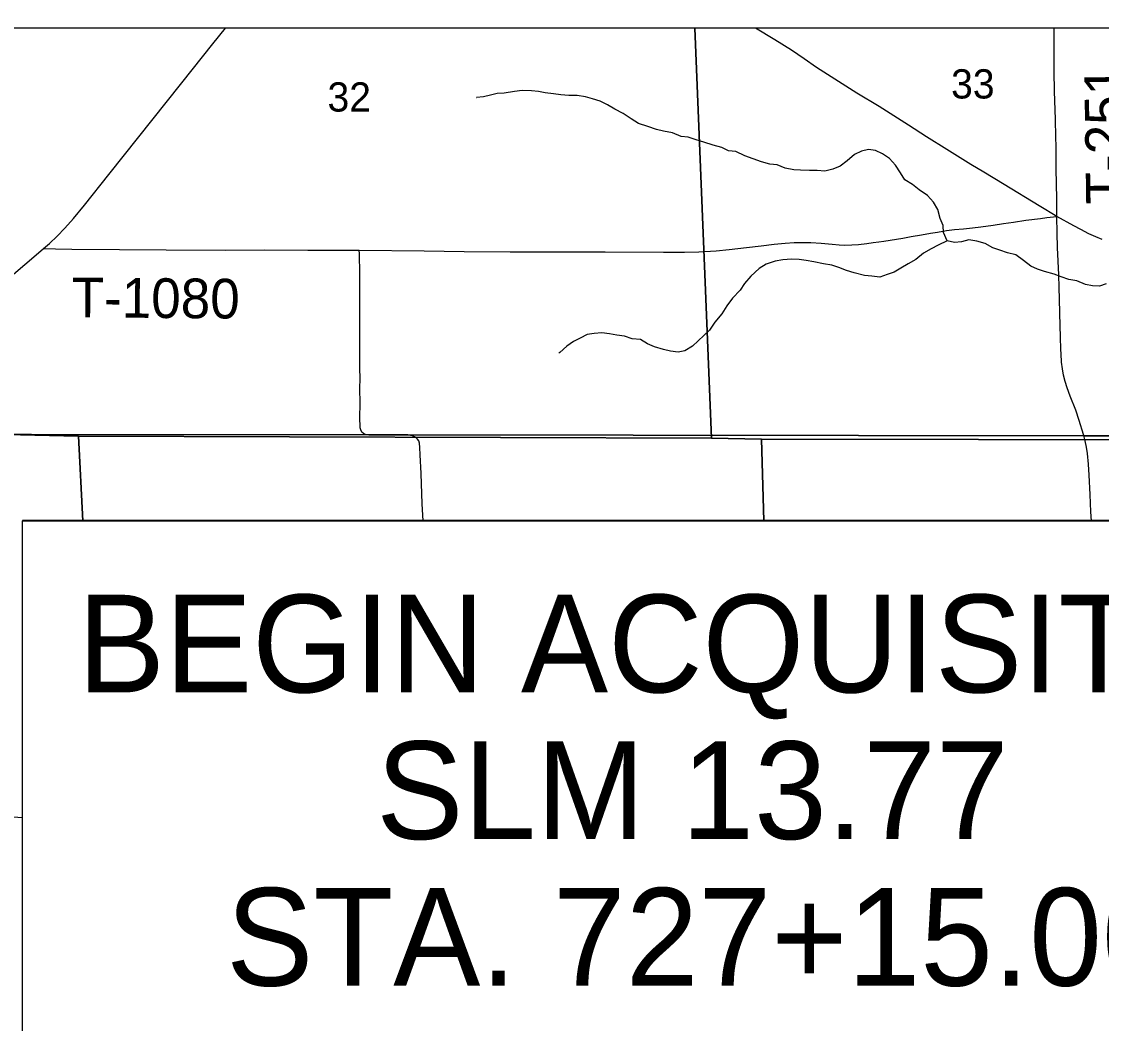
# Model space of a CAD drawing. Extents: x 0 to 34, y 0 to 22.
# Drawn here: x 4.127 to 5.673, y 16.027 to 17.462 of the extents above; entities that cross this region are included whole.
import ezdxf

# ---------------------------------------------------------------- set-up
doc = ezdxf.new("R2010")
doc.units = 0
for name, color, linetype in [('Default', 7, 'Continuous'), ('GM_X_County_Road', 7, 'Continuous'), ('GM_X_Interstate_Route', 7, 'Continuous'), ('GM_X_Minor_River', 7, 'Continuous'), ('GM_X_Section', 7, 'Continuous'), ('GM_X_Section_Text', 7, 'Continuous'), ('GM_X_State_Route', 7, 'Continuous'), ('GM_X_Township_Road', 7, 'Continuous'), ('GM_X_Township_Road_Text', 7, 'Continuous'), ('GM_X_US_Route', 7, 'Continuous'), ('SH_Text', 7, 'Continuous')]:
    doc.layers.add(name, color=color, linetype=linetype)

msp = doc.modelspace()

# ---------------------------------------------------------------- linework, layer by layer
at = {"layer": 'Default'}
for points in [[(4.0336, 18.2003), (5.9872, 18.2003), (5.9872, 17.4527), (4.0336, 17.4527)], [(4.1282, 16.747), (6.0753, 16.747), (6.0753, 16), (6.0818, 16), (6.0818, 16.7475), (4.1282, 16.7475)], [(4.1282, 16.747), (6.0818, 16.747), (6.0818, 15.9995), (4.1282, 15.9995)]]:
    msp.add_lwpolyline(points, close=True, dxfattribs=at)
at = {"layer": 'GM_X_County_Road'}
for points in [[(5.6485, 16.8672), (5.6483, 16.8682), (5.6477, 16.8705), (5.6414, 16.8909), (5.6363, 16.9056), (5.6285, 16.9258), (5.6242, 16.9376), (5.6214, 16.9465), (5.6191, 16.9556), (5.6174, 16.9648), (5.6161, 16.9741), (5.6153, 16.9864), (5.6151, 16.9926), (5.6146, 17.0107), (5.6141, 17.0263), (5.6136, 17.0451), (5.613, 17.0647), (5.6126, 17.081), (5.6121, 17.0991), (5.6112, 17.1189), (5.6105, 17.1383), (5.6099, 17.1588), (5.6094, 17.183)], [(5.6589, 16.747), (5.6581, 16.7599), (5.6572, 16.7848), (5.6556, 16.8126), (5.6547, 16.8281), (5.6532, 16.8435), (5.6518, 16.8526), (5.6499, 16.8616), (5.6485, 16.8672)]]:
    msp.add_lwpolyline(points, dxfattribs=at)
at = {"layer": 'GM_X_Interstate_Route'}
for points in [[(3.6554, 16.8713), (4.6269, 16.8701), (4.6731, 16.8702), (4.6802, 16.8702), (5.6481, 16.8687), (5.8525, 16.8686)], [(5.8525, 16.8686), (5.6481, 16.8687), (4.6802, 16.8702), (4.6731, 16.8702), (4.6269, 16.8701), (3.6554, 16.8713)]]:
    msp.add_lwpolyline(points, dxfattribs=at)
at = {"layer": 'GM_X_Minor_River'}
for points in [[(5.68, 17.0862), (5.6705, 17.0832), (5.6603, 17.0837), (5.6504, 17.0853), (5.638, 17.0907), (5.6266, 17.0924), (5.6157, 17.0963), (5.6055, 17.1005), (5.5915, 17.1041), (5.5817, 17.1072), (5.5719, 17.1119), (5.5614, 17.1196), (5.5508, 17.128), (5.5387, 17.1308), (5.5278, 17.1347), (5.5176, 17.1382), (5.5067, 17.1444), (5.495, 17.1475), (5.4832, 17.1495), (5.4726, 17.1466), (5.4627, 17.1456), (5.4525, 17.1479), (5.447, 17.1598), (5.4467, 17.17), (5.4422, 17.1799), (5.4389, 17.1928), (5.4326, 17.2032), (5.4239, 17.2131), (5.4123, 17.2212), (5.4025, 17.2285), (5.3916, 17.2354), (5.3856, 17.2454), (5.3785, 17.2564), (5.3695, 17.266), (5.3597, 17.2725), (5.3499, 17.2772), (5.3397, 17.2788), (5.3298, 17.2763), (5.3195, 17.2714), (5.3092, 17.2624), (5.2993, 17.2549), (5.2887, 17.2505), (5.2769, 17.2479), (5.266, 17.2488), (5.2553, 17.2485), (5.2425, 17.249), (5.2326, 17.2495), (5.2205, 17.2519), (5.2088, 17.2566), (5.1982, 17.2578), (5.1862, 17.261), (5.1745, 17.2656), (5.1624, 17.2699), (5.1499, 17.2761), (5.1393, 17.277), (5.1295, 17.2816), (5.1171, 17.2852), (5.1038, 17.2895), (5.0929, 17.2926), (5.0812, 17.2965), (5.0713, 17.2974), (5.0589, 17.3024), (5.046, 17.3048), (5.0362, 17.3072), (5.0238, 17.3119), (5.0102, 17.3158), (5, 17.3227), (4.9883, 17.3304), (4.9766, 17.3366), (4.9661, 17.3428), (4.9555, 17.3478), (4.9446, 17.3513), (4.9344, 17.3541), (4.9223, 17.3561), (4.9105, 17.3559), (4.8992, 17.3571), (4.8886, 17.3583), (4.8769, 17.36), (4.867, 17.362), (4.8572, 17.3628), (4.8439, 17.3633), (4.8326, 17.3619), (4.8182, 17.3594), (4.8079, 17.3588), (4.7984, 17.3566), (4.7886, 17.3544), (4.7783, 17.3534), (4.7787, 17.3533)], [(5.4525, 17.1479), (5.4396, 17.1416), (5.4293, 17.1364), (5.4183, 17.1301), (5.4076, 17.1214), (5.3966, 17.1151), (5.3859, 17.1087), (5.3764, 17.1032), (5.3666, 17.0998), (5.3559, 17.0961), (5.3446, 17.0974), (5.334, 17.0983), (5.3192, 17.1022), (5.3083, 17.1057), (5.297, 17.1096), (5.2871, 17.1131), (5.2754, 17.1151), (5.2614, 17.1179), (5.2505, 17.1196), (5.2406, 17.1215), (5.2293, 17.1217), (5.2168, 17.1206), (5.2058, 17.1189), (5.1929, 17.1148), (5.183, 17.1085), (5.1711, 17.0972), (5.1623, 17.087), (5.1558, 17.0772), (5.1447, 17.0659), (5.1367, 17.055), (5.1298, 17.0437), (5.1198, 17.0313), (5.1118, 17.02), (5.0874, 16.9974), (5.0767, 16.9907), (5.0672, 16.9885), (5.0562, 16.9898), (5.046, 16.9925), (5.0332, 16.9961), (5.0234, 17.0007), (5.0132, 17.0065), (5.0011, 17.0078), (4.9905, 17.0113), (4.9792, 17.0129), (4.9686, 17.0149), (4.958, 17.0162), (4.947, 17.0155), (4.9368, 17.0137), (4.9269, 17.0085), (4.9174, 17.0037), (4.9079, 16.9973), (4.8976, 16.9879), (4.8964, 16.9872)]]:
    msp.add_lwpolyline(points, dxfattribs=at)
at = {"layer": 'GM_X_Section'}
for points in [[(5.0909, 17.4527), (5.1149, 16.8654), (5.1862, 16.8638), (6.1193, 16.8628), (6.1027, 17.8448), (5.9868, 17.8455), (5.9868, 17.4527)], [(4.1005, 17.4527), (4.1045, 16.8706), (4.2083, 16.8683), (5.1149, 16.8654), (5.0909, 17.4527)], [(4.2148, 16.747), (4.2083, 16.8683), (4.1045, 16.8706), (3.2153, 16.8759), (3.2082, 15.8593), (4.2651, 15.8107), (4.2549, 16), (4.1282, 16), (4.1282, 16.747)], [(5.1896, 16.747), (5.1862, 16.8638), (5.1149, 16.8654), (4.2083, 16.8683), (4.2148, 16.747)], [(5.2115, 16), (5.2159, 15.85), (6.2093, 15.844), (6.1739, 16.8615), (6.1193, 16.8628), (5.1862, 16.8638), (5.1896, 16.747), (6.0753, 16.747), (6.0753, 16)]]:
    msp.add_lwpolyline(points, close=True, dxfattribs=at)
at = {"layer": 'GM_X_State_Route'}
msp.add_lwpolyline([(5.674, 17.15), (5.6651, 17.1536), (5.6552, 17.158), (5.6436, 17.1641), (5.6338, 17.1695), (5.6094, 17.183), (5.584, 17.1982), (5.534, 17.2287), (5.5046, 17.2461), (5.4861, 17.2575), (5.4518, 17.2788), (5.4228, 17.2969), (5.3967, 17.3137), (5.3757, 17.3271), (5.3547, 17.3402), (5.3228, 17.3595), (5.2965, 17.3762), (5.2652, 17.3963), (5.2475, 17.4088), (5.2295, 17.421), (5.2057, 17.4358), (5.178, 17.4527)], dxfattribs=at)
at = {"layer": 'GM_X_Township_Road'}
for points in [[(5.6094, 17.183), (5.6094, 17.201), (5.6094, 17.2123), (5.6089, 17.2253), (5.6089, 17.2339), (5.6084, 17.2469), (5.6084, 17.2577), (5.6084, 17.2704), (5.6083, 17.2846), (5.6078, 17.295), (5.6078, 17.3045), (5.6073, 17.3139), (5.6073, 17.3222), (5.606, 17.3617), (5.6054, 17.3907), (5.6054, 17.408), (5.6056, 17.4336), (5.6055, 17.4527)], [(4.6103, 17.1344), (4.7036, 17.1336), (4.7605, 17.1327), (4.8266, 17.1323), (4.8715, 17.1321), (4.9158, 17.1321), (4.9627, 17.1321), (5.0461, 17.1318), (5.0761, 17.1318), (5.0968, 17.1323), (5.1216, 17.1339), (5.1401, 17.1357), (5.1648, 17.1383), (5.1859, 17.1409), (5.2048, 17.143), (5.2203, 17.1446), (5.2331, 17.1455), (5.245, 17.1458), (5.2571, 17.1455), (5.2718, 17.1446), (5.2874, 17.1433), (5.2977, 17.1422), (5.306, 17.1417), (5.3158, 17.1422), (5.3254, 17.1429), (5.3375, 17.1443), (5.3461, 17.1456), (5.3546, 17.1468), (5.3614, 17.1476), (5.3887, 17.1519), (5.4009, 17.154), (5.4156, 17.1565), (5.4286, 17.1589), (5.4383, 17.1606), (5.4515, 17.1626), (5.4627, 17.164), (5.4755, 17.1653), (5.4886, 17.1665), (5.5007, 17.1681), (5.5183, 17.1706), (5.533, 17.1729), (5.5474, 17.1749), (5.565, 17.1774), (5.5858, 17.1802), (5.5951, 17.1816), (5.6094, 17.183)], [(4.1581, 17.1368), (4.1757, 17.1365), (4.1987, 17.136), (4.2671, 17.1356), (4.3338, 17.1353), (4.4187, 17.1348), (4.4744, 17.1352), (4.5367, 17.1348), (4.5969, 17.1346), (4.6103, 17.1344)], [(4.6281, 16.8696), (4.6271, 16.8696), (4.624, 16.8698), (4.6222, 16.87), (4.6193, 16.8706), (4.6166, 16.8719), (4.6141, 16.8741), (4.6125, 16.8773), (4.612, 16.8802), (4.6116, 16.8835), (4.6115, 16.8928), (4.6116, 16.9176), (4.6115, 16.9348), (4.6116, 16.9529), (4.6114, 16.9636), (4.6114, 16.9784), (4.6112, 16.9948), (4.6115, 17.0258), (4.6115, 17.0816), (4.6114, 17.1095), (4.611, 17.1209), (4.6106, 17.1296), (4.6103, 17.1344)], [(4.6812, 16.8695), (4.6804, 16.8696), (4.6733, 16.8697), (4.6281, 16.8696)], [(4.7019, 16.747), (4.7007, 16.7715), (4.699, 16.815), (4.6977, 16.8418), (4.6974, 16.8519), (4.6967, 16.8583), (4.6956, 16.8616), (4.694, 16.8641), (4.6918, 16.866), (4.6895, 16.8673), (4.6867, 16.8686), (4.6838, 16.8692), (4.6812, 16.8695)], [(3.7409, 16.3372), (3.755, 16.3365), (3.7767, 16.3354), (3.8605, 16.3319), (3.8823, 16.3311), (3.9351, 16.3295), (3.9909, 16.3275), (4.0099, 16.3268), (4.05, 16.3254), (4.0717, 16.3246), (4.0997, 16.3237), (4.1214, 16.3228), (4.1282, 16.3225)]]:
    msp.add_lwpolyline(points, dxfattribs=at)
at = {"layer": 'GM_X_US_Route'}
msp.add_lwpolyline([(4.0697, 17.0615), (4.1479, 17.1278), (4.1581, 17.1368), (4.1667, 17.1442), (4.178, 17.1549), (4.1887, 17.1661), (4.2011, 17.1802), (4.217, 17.1993), (4.252, 17.2429), (4.3565, 17.3743), (4.401, 17.4303), (4.4189, 17.4527)], dxfattribs=at)
at = {"layer": 'SH_Text'}
for points in [[(4.0336, 18.2003), (5.9868, 18.2003), (5.9868, 17.4527), (4.0336, 17.4527)], [(4.1282, 16.747), (6.0753, 16.747), (6.0753, 15.9995), (4.1282, 15.9995)]]:
    msp.add_lwpolyline(points, close=True, dxfattribs=at)

# ---------------------------------------------------------------- texts
at = {"layer": 'Default'}
for s, p in [('BEGIN ACQUISITION', (4.2074, 16.5014)), ('SLM 13.77', (4.6348, 16.2914)), ('STA. 727+15.00', (4.4198, 16.0814))]:
    msp.add_text(s, height=0.14, dxfattribs=at).set_placement(p)
at = {"layer": 'GM_X_Section_Text'}
for s, p in [('33', (5.4579, 17.3518)), ('32', (4.565, 17.3331))]:
    msp.add_text(s, height=0.04186, rotation=0, dxfattribs=at).set_placement(p)
at = {"layer": 'GM_X_Township_Road_Text'}
for s, rotation, p in [('T-251', 90.8309, (5.7082, 17.2007)), ('T-1080', 359.5312, (4.1984, 17.0386))]:
    msp.add_text(s, height=0.05682, rotation=rotation, dxfattribs=at).set_placement(p)

doc.saveas('drawing.dxf')
